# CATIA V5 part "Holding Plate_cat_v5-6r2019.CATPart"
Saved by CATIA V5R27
Part number: Holding Plate
Bounding box of the stored display mesh (mm): x -16 to 16, y -16 to 16, z 0 to 7
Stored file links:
  E:\_Deepak\2017_Deepak\CATIA\Resources\Tutorial Files\Tutorials\c16_catia_v5_6r2016_tut\Bench vice\Holding Plate_cat_v5-6r2016.CATPart
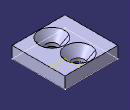
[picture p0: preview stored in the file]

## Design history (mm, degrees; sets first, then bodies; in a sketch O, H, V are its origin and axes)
Body1 (main body)
  Sketch1 on xy-plane, origin (0, 0, 0), H (1, 0, 0), V (0, 1, 0)
    line L1 (-16, 16) -> (16, 16)
    line L2 (16, 16) -> (16, -16)
    line L3 (16, -16) -> (-16, -16)
    line L4 (-16, -16) -> (-16, 16)
    construction line L5 (-16, 16) -> (16, -16)
    length L2 = 32
    length L3 = 32
    distance H L3 = 16
    distance V L4 = 16
    horizontal: L1 H, L3 H
    vertical: L2 V, L4 V
  Pad1: profile Sketch1, direction (0, 0, 1), length 7
  Sketch2 on face of Pad1, origin (-0.9262, 8.6399, 7), H (1, 0, 0), V (0, 1, 0)
    point P1 (0.9262, -0.6399)
    reference intersected line E1 through (0.9262, 0) direction (0, 1) from yz-plane
    reference projected line E3 (-15.0738, 7.3601) -> (16.9262, 7.3601) from edge of Pad1
    distance P1 E3 = 8
    coincidence: E1 P1
  Hole1: placed by Sketch2, at (0, 8, 7) direction (0, 0, -1), diameter 7, depth 10, countersink depth 5, countersink angle 80
  Mirror1: of Hole1, about zx-plane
